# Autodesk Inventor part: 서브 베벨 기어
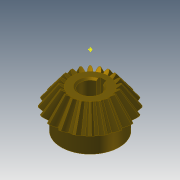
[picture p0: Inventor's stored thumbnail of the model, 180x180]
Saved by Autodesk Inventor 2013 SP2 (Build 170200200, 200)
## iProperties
Created: 2014-10
Part Number: 서브 베벨 기어
Material: Steel, Mild
Document SubType Name: Modeling
Designer: KYOUNG IL JANG
Categories: <?xml version="1.0" encoding="UTF-16"?> <MemberInstance><Categories><FamilyTemplate><FamilyTemplateParameter ValueType="xs:double" Id="1" ObjectReferenceKey="da
Mass: 134.866 g
Surface Area: 63.6518 cm^2
Volume: 17.1585 cm^3
Density: 7.86 g/cm^3
CustomPartVersion: 1
Company: 한국ATC센터
Author: KYOUNG IL JANG
Revision Number: 1
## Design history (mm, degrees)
node "맨 위 점"
node "메쉬 평면2"
sketch "톱니 본체 스케치"
  geometry: L1 (0, 0)-(18.003, -31.331); L2 (18.003, -31.331)-(21.664, -28.891); L3 (21.664, -28.891)-(0, 0); L4 (20, -30)-(0, 0); L5 (10.813, -18.818)-(13.012, -17.352); L6 (18.003, -31.331)-(10.813, -18.818); L7 (21.664, -28.891)-(13.012, -17.352); L8 (0, -39.387)-(0, 6.564) reference; L9 (0, -30)-(21.664, -30)
  constraints: 16 end point, 4 point on line, 3 perpendicular, 2 collinear, 1 horizontal alignment, 1 vertical alignment
  dimensions: "d0" = 40 diameter of L4.start L8 (= da_de); "d1" = 36.00616 diameter of L1.end L8 (= da_dfe); "d2" = 43.3282 diameter of L2.end L8 (= da_dae); "d3" = 14.4 distance between parallel lines of L2 L5 (= da_b); "d4" = 28.8906 vertical distance of L2.end L1.start (= da_ve)
revolve "톱니 본체" sketch "톱니 본체 스케치" stored, may be unused: angle "d5" = 90 deg
node "시작점"
node "톱니 평면"
sketch "시작 스케치"
  geometry: L1 (0, -23.505)-(0, 10.645) reference; L2 (-0.834, -2.928)-(0.834, -2.928); A1 r 8.898 centre (-9.698, -3.713) between (-0.834, -2.928) and (-3.903, 3.04); A2 r 8.898 centre (9.698, -3.713) between (3.903, 3.04) and (0.834, -2.928); A3 r 27.357 centre (0, -24.037) between (3.903, 3.04) and (-3.903, 3.04); 1 further point
  constraints: 6 point on circle, 3 centre point, 3 symmetric about line, 2 end point, 1 coincident, 1 perpendicular, 1 other
  dimensions: "d7" = 8.89846 radius of A1 (= fd_rr); "d8" = 9.69794 horizontal distance of point (0, -24.037) A1.centre (= fd_x); "d9" = 20.32439 vertical distance of point (0, -24.037) A1.centre (= fd_y); "d57" = 27.35701 radius of A3 (= 0.5 x fd_dva + 0.3 x da_he); "d58" = 21.10901 distance from line of A3.centre L2 (= 0.5 x fd_dva - 1.12 x da_he)
node "끝점"
  node "끝 평면"
sketch "3D 스케치 오른쪽"
  node "Helical Curve Right" dims "d65" = 229.90621 (computed from da_dm, da_delta, da_beta), "d66" = 31.5, "d67" = 40 (= da_de), "d68" = -5.88003 (= -da_delta), "d69" = 12.16458 (computed from fd_loft, da_delta)
node "끝 평면 오른쪽"
sketch "끝 스케치 오른쪽"
  geometry: L1 (0, -22.649)-(0, 12.15) reference; L2 (-0.497, -1.72)-(0.497, -1.72); A1 r 5.299 centre (-5.775, -2.187) between (-0.497, -1.72) and (-2.324, 1.834); A2 r 5.299 centre (5.775, -2.187) between (2.324, 1.834) and (0.497, -1.72); A3 r 16.291 centre (0, -14.29) between (2.324, 1.834) and (-2.324, 1.834); 1 further point
  constraints: 6 point on circle, 3 centre point, 3 symmetric about line, 2 end point, 1 coincident, 1 perpendicular, 1 other
  dimensions: "d70" = 5.77526 horizontal distance of A3.centre A1.centre (computed from fd_x, fd_ratio); "d71" = 12.10346 vertical distance of point (0, -14.29) A1.centre (computed from fd_y, fd_ratio); "d72" = 5.29916 radius of A1 (computed from fd_rr, fd_ratio); "d73" = 12.57071 distance from line of point (0, -14.29) L2 (computed from d58, fd_ratio); "d74" = 16.29149 radius of A3 (computed from d57, fd_ratio)
feature "로프트 오른쪽" sketch "끝 스케치 오른쪽" dims "d75" = 0, "d77" = 0, "d79" = 0, "d80" = 90 deg, "d85" = 20, "d92" = 90 deg, "d93" = 90 deg, "da_teethtype" = 0 [user parameter]
sketch "3D 스케치 왼쪽"
  node "Helical Curve Left" dims "d26" = 229.90621 (computed from da_dm, da_delta, da_beta), "d27" = 12.16458 (computed from fd_loft, da_delta), "d28" = 40 (= da_de), "d29" = -5.88003 (= -da_delta)
node "끝 평면 왼쪽"
sketch "끝 스케치 왼쪽" dims "d56" = 10.82768 (derived)
  geometry: L1 (0, -35.087)-(0, 18.089) reference; L2 (-0.497, -1.716)-(0.497, -1.716); A1 r 5.299 centre (-5.775, -2.183) between (-0.497, -1.716) and (-2.324, 1.838); A2 r 5.299 centre (5.775, -2.183) between (2.324, 1.838) and (0.497, -1.716); A3 r 16.291 centre (0, -14.287) between (2.324, 1.838) and (-2.324, 1.838); 2 further points; 1 other entity
  constraints: 6 point on circle, 3 centre point, 3 symmetric about line, 2 end point, 1 coincident, 2 other
  dimensions: "d30" = 5.29916 radius of A1 (computed from fd_rr, fd_ratio); "d31" = 5.77526 horizontal distance of point (0, -14.287) A1.centre (computed from fd_x, fd_ratio); "d32" = 12.10346 vertical distance of A1.centre point (0, -14.287) (computed from fd_y, fd_ratio); "d61" = 16.29149 radius of A3 (computed from d57, fd_ratio); "d62" = 12.57071 distance from line of point (0, -14.287) L2 (computed from d58, fd_ratio)
feature "로프트 왼쪽" sketch "끝 스케치 왼쪽" dims "d35" = 0, "d37" = 0, "d39" = 0, "d40" = 90 deg, "d84" = 10, "d90" = 90 deg, "d91" = 90 deg, "da_teethtype" = 0 [user parameter]
sketch "본체 스케치"
  geometry: L1 (0, -35.038)-(0, -19.531) reference; L2 (18.003, -31.331)-(10.813, -18.818) reference; L3 (10.813, -18.818)-(0, -18.818); L4 (18.003, -31.331)-(0, -31.331)
  constraints: 4 end point, 2 perpendicular, 2 point on line
revolve "본체 고정" sketch "본체 스케치" stored, may be unused: angle "d46" = 90 deg
feature "피치 지름" dims angle "d47" = 90 deg
sketch "스케치8"
  geometry: C1 r 17 at (0, 0); 1 further point
  constraints: 1 centre point, 1 coincident
  dimensions: "d94" = 34 diameter of C1
extrude "돌출1" join sketch "스케치8" distance "d95" = 10; taper "d96" = 0 deg
sketch "스케치9"
  geometry: 1 further point
hole "구멍1" sketch "스케치9" at (0, 0) diameter "d97" = 12; stored, may be unused: countersink angle "d101" = 90 deg, drill point angle "d103" = 118 deg; dims "d98" = 6, "d99" = 4, "d100" = 2, "d102" = 8
sketch "스케치10"
  geometry: 1 further point
sketch "스케치11"
  geometry: 1 further point
sketch "스케치12"
  geometry: L1 (-2, 5.657)-(-2, 7.8); L2 (-2, 7.8)-(2, 7.8); L3 (2, 7.8)-(2, 5.657); A1 r 6 centre (0, 0) between (-2, 5.657) and (2, 5.657) reference; 1 further point
  constraints: 6 end point, 2 parallel, 2 point on circle, 1 perpendicular, 1 vertical
  dimensions: "d104" = 4 distance of L1.end L2.end; "d105" = 13.8 dimension on A1 L2
extrude "돌출2" cut sketch "스케치12" stored distance "d106" = 7; taper "d107" = 0 deg
chamfer "모따기1" distance "d108" = 1; stored, may be unused: second distance "d109" = 2, angle "d110" = 45 deg
body "Solid1"
feature "로프트" dims "d17" = 0, "d18" = 90 deg, "d19" = 0, "d20" = 90 deg, "d89" = 0, "da_teethtype" = 0 [user parameter]
pattern_circular "원형 패턴" dims angle "d22" = 360 deg, "d88" = 0, "da_teethtype" = 0 [user parameter]
pattern_circular "원형 패턴 오른쪽" dims angle "d82" = 360 deg, "da_teethtype" = 0 [user parameter]
pattern_circular "원형 패턴 왼쪽" dims angle "d42" = 360 deg, "da_teethtype" = 0 [user parameter]
sketch "끝 스케치"
  geometry: L1 (0, -15.359)-(0, 6.983) reference; L2 (-0.497, -1.72)-(0.497, -1.72); A1 r 5.299 centre (-5.775, -2.187) between (-0.497, -1.72) and (-2.324, 1.834); A2 r 5.299 centre (5.775, -2.187) between (2.324, 1.834) and (0.497, -1.72); A3 r 16.291 centre (0, -14.29) between (2.324, 1.834) and (-2.324, 1.834); 1 further point
  constraints: 6 point on circle, 3 centre point, 3 symmetric about line, 2 end point, 1 coincident, 1 other
  dimensions: "d12" = 5.29916 radius of A1 (computed from fd_rr, fd_ratio); "d15" = 5.77526 horizontal distance of A1.centre point (0, -14.29) (computed from fd_x, fd_ratio); "d16" = 12.10346 vertical distance of A1.centre point (0, -14.29) (computed from fd_y, fd_ratio); "d59" = 16.29149 radius of A3 (computed from d57, fd_ratio); "d60" = 12.57071 distance from line of A3.centre L2 (computed from d58, fd_ratio)
sketch "Sketch6"
  geometry: L1 (20, -30)-(0, 0) reference; L2 (0, -37.8)-(0, 6.3) reference
body "Srf1"
other parameters: "da_b" = 14.4 [user parameter; used in 2 equation terms], "da_de" = 40 [user parameter; used in 4 equation terms], "da_dae" = 43.3282 [user parameter; used in 2 equation terms], "da_dfe" = 36.00616 [user parameter; used in 1 equation term], "da_le" = 36.05551 [user parameter; used in 1 equation term], "da_omega" = 90 deg [user parameter; used in 1 equation term], "da_beta" = 0 [user parameter; used in 2 equation terms], "da_delta" = 5.88003 [user parameter; used in 8 equation terms], "da_alpha" = 20 deg [user parameter; used in 2 equation terms], "da_he" = 4.4 [user parameter; used in 4 equation terms], "da_ve" = 28.8906 [user parameter; used in 1 equation term], "fd_dv" = 48.07402 (computed from da_de, da_delta) [user parameter; used in 1 equation term], "fd_dva" = 52.07402 (computed from da_dae, da_delta) [user parameter; used in 3 equation terms], "fd_dvb" = 45.1748 (computed from fd_dv, da_alpha) [user parameter; used in 2 equation terms], "da_zv" = 240.37008 [user parameter; used in 1 equation term], "fd_loft" = 14.62 (= da_b + 0.05 x da_he) [user parameter; used in 4 equation terms], "fd_ratio" = 5.95514 (computed from da_le, fd_loft) [user parameter; used in 15 equation terms], "fd_rr" = 8.89846 (computed from fd_dd, fd_dvb) [user parameter; used in 6 equation terms], "fd_angle" = 0.66075 (computed from da_zv) [user parameter; used in 4 equation terms], "fd_x1" = 1.58709 (computed from da_dvw, fd_angle) [user parameter; used in 1 equation term], "fd_y1" = 23.98456 (computed from da_dvw, fd_angle) [user parameter; used in 1 equation term], "fd_x2" = 8.11084 (computed from fd_rr, fd_angle2, fd_angle) [user parameter; used in 1 equation term], "fd_y2" = 3.66016 (computed from fd_rr, fd_angle2, fd_angle) [user parameter; used in 1 equation term], "fd_x" = 9.69794 (= fd_x1 + fd_x2) [user parameter; used in 4 equation terms], "fd_y" = 20.32439 (= fd_y1 - fd_y2) [user parameter; used in 4 equation terms], "fd_angle2" = 3.57832 (computed from fd_dvb, fd_dd, da_alpha) [user parameter; used in 2 equation terms], "fd_dd" = 48.55402 (= fd_dva - 0.8 x da_he) [user parameter; used in 2 equation terms], "da_dvw" = 48.07402 [user parameter; used in 2 equation terms], "d11" = 14.62 (= fd_loft), "da_dm" = 32.01232 [user parameter; used in 2 equation terms], "da_x" = 0 [user parameter], "da_m" = 2 [user parameter], "d48" = 0, "d49" = 0, "d50" = 90 deg (= da_omega), "d51" = 9 deg (computed from da_z), "d52" = 0, "d53" = 0, "d54" = 0
